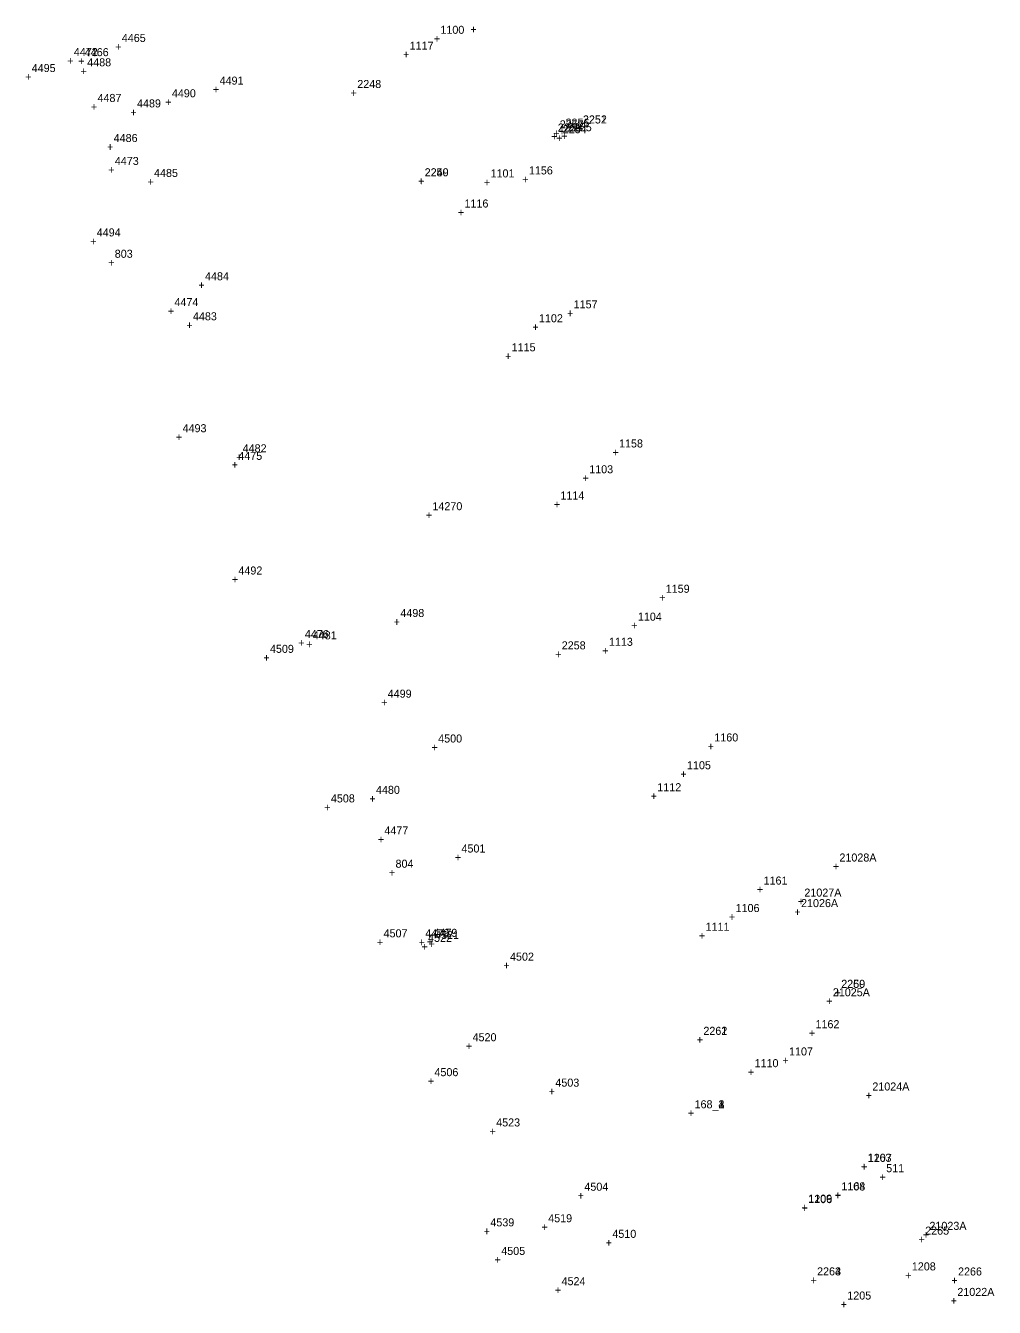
# Model space of a CAD drawing. Extents: x 1036751 to 1042192, y 772604 to 785439.
# Drawn here: x 1037008.7 to 1037310, y 782621.3 to 783020 of the extents above; entities that cross this region are included whole.
import ezdxf

# ---------------------------------------------------------------- set-up
doc = ezdxf.new("R2010")
doc.units = 0
for name, color, linetype in [('S_Control_Temp_Traverse', 7, 'Continuous'), ('S_Control_Traverse_Point', 7, 'Continuous'), ('S_Drainage_Culvert_Top', 7, 'Continuous'), ('S_Drainage_Invert', 7, 'Continuous'), ('S_Drainage_RipRap', 7, 'Continuous'), ('S_Ground_Elevation', 7, 'Continuous'), ('S_Roadway_Centerline', 7, 'Continuous'), ('S_Roadway_Edge_Pavement', 7, 'Continuous'), ('S_Roadway_Edge_TW', 7, 'Continuous'), ('S_Traffic_Sign_SinglePost', 7, 'Continuous'), ('S_Utilities_Pole_Power', 7, 'Continuous')]:
    doc.layers.add(name, color=color, linetype=linetype)

msp = doc.modelspace()

# ---------------------------------------------------------------- texts
at = {"layer": 'S_Control_Temp_Traverse'}
for s, p in [('803', (1037036.43, 782947.8)), ('803', (1037036.43, 782947.8)), ('803', (1037036.43, 782947.8)), ('803', (1037036.43, 782947.8)), ('+', (1037034.37, 782945.05)), ('+', (1037034.37, 782945.05)), ('+', (1037034.37, 782945.05)), ('+', (1037034.37, 782945.05)), ('+', (1037121.71, 782755.28)), ('+', (1037121.71, 782755.28)), ('+', (1037121.71, 782755.28)), ('+', (1037121.71, 782755.28)), ('804', (1037123.77, 782758.03)), ('804', (1037123.77, 782758.03)), ('804', (1037123.77, 782758.03)), ('804', (1037123.77, 782758.03)), ('168', (1037216.79, 782683.19)), ('168_1', (1037216.79, 782683.19)), ('168_3', (1037216.79, 782683.19)), ('168_2', (1037216.79, 782683.19)), ('168_4', (1037216.79, 782683.19)), ('+', (1037214.73, 782680.44)), ('+', (1037214.73, 782680.44)), ('+', (1037214.73, 782680.44)), ('+', (1037214.73, 782680.44)), ('+', (1037214.73, 782680.44))]:
    msp.add_text(s, height=2.5, dxfattribs=at).set_placement(p)
at = {"layer": 'S_Control_Traverse_Point'}
for s, p in [('511', (1037276.41, 782663.31)), ('511', (1037276.41, 782663.31)), ('511', (1037276.41, 782663.31)), ('511', (1037276.41, 782663.31)), ('511', (1037276.41, 782663.31)), ('+', (1037274.35, 782660.56)), ('+', (1037274.35, 782660.56)), ('+', (1037274.35, 782660.56)), ('+', (1037274.35, 782660.56)), ('+', (1037274.35, 782660.56))]:
    msp.add_text(s, height=2.5, dxfattribs=at).set_placement(p)
at = {"layer": 'S_Drainage_Culvert_Top'}
for s, p in [('+', (1037179.99, 782986.83)), ('2251', (1037182.05, 782989.58)), ('2250', (1037132.83, 782973.15)), ('+', (1037130.77, 782970.4)), ('2260', (1037262.4, 782720.64)), ('+', (1037260.34, 782717.89)), ('+', (1037217.47, 782703.28)), ('2261', (1037219.53, 782706.03)), ('2265', (1037288.53, 782643.88)), ('+', (1037286.47, 782641.13)), ('2264', (1037254.9, 782631.21)), ('+', (1037252.84, 782628.46))]:
    msp.add_text(s, height=2.5, dxfattribs=at).set_placement(p)
at = {"layer": 'S_Drainage_Invert'}
for s, p in [('+', (1037180.01, 782986.84)), ('2252', (1037182.07, 782989.59)), ('2249', (1037132.86, 782973.12)), ('+', (1037130.8, 782970.37)), ('2259', (1037262.43, 782720.66)), ('+', (1037260.37, 782717.91)), ('+', (1037217.48, 782703.3)), ('2262', (1037219.54, 782706.05)), ('2263', (1037254.9, 782631.19)), ('+', (1037252.84, 782628.44))]:
    msp.add_text(s, height=2.5, dxfattribs=at).set_placement(p)
at = {"layer": 'S_Drainage_RipRap'}
for s, p in [('21028A', (1037261.85, 782759.96)), ('+', (1037259.79, 782757.21)), ('21027A', (1037250.95, 782749.05)), ('+', (1037248.89, 782746.3)), ('21026A', (1037249.91, 782745.78)), ('+', (1037247.85, 782743.03)), ('+', (1037257.74, 782715.29)), ('21025A', (1037259.8, 782718.04)), ('21024A', (1037272.09, 782688.72)), ('+', (1037270.03, 782685.97)), ('21023A', (1037289.85, 782645.37)), ('+', (1037287.78, 782642.62)), ('21022A', (1037298.53, 782624.81)), ('+', (1037296.47, 782622.06))]:
    msp.add_text(s, height=2.5, dxfattribs=at).set_placement(p)
at = {"layer": 'S_Ground_Elevation'}
for s, p in [('4465', (1037038.62, 783014.94)), ('4466', (1037027.1, 783010.52)), ('+', (1037036.56, 783012.19)), ('+', (1037025.04, 783007.77)), ('4488', (1037027.87, 783007.36)), ('+', (1037025.81, 783004.61)), ('+', (1037066.98, 782998.92)), ('4491', (1037069.04, 783001.67)), ('4487', (1037031.06, 782996.27)), ('4489', (1037043.36, 782994.58)), ('+', (1037052.14, 782994.98)), ('4490', (1037054.2, 782997.73)), ('+', (1037029, 782993.52)), ('+', (1037041.3, 782991.83)), ('2253', (1037174.25, 782987.08)), ('2257', (1037174.85, 782988.07)), ('2254', (1037175.79, 782986.55)), ('2256', (1037176.64, 782988.6)), ('2255', (1037177.36, 782987.16)), ('4486', (1037036.09, 782983.81)), ('+', (1037172.18, 782984.33)), ('+', (1037172.79, 782985.32)), ('+', (1037173.73, 782983.8)), ('+', (1037174.58, 782985.85)), ('+', (1037175.3, 782984.41)), ('+', (1037034.03, 782981.06)), ('4485', (1037048.65, 782972.94)), ('+', (1037046.59, 782970.19)), ('4484', (1037064.51, 782940.8)), ('+', (1037062.45, 782938.05)), ('4483', (1037060.75, 782928.34)), ('+', (1037058.69, 782925.59)), ('4482', (1037076.21, 782887.27)), ('+', (1037074.15, 782884.52)), ('14270', (1037135.25, 782869.26)), ('+', (1037133.19, 782866.51)), ('4498', (1037125.27, 782836.03)), ('+', (1037123.21, 782833.28)), ('4481', (1037098.03, 782829.08)), ('+', (1037095.96, 782826.33)), ('4499', (1037121.34, 782810.94)), ('+', (1037119.28, 782808.19)), ('4500', (1037137.04, 782796.99)), ('+', (1037134.98, 782794.24)), ('4480', (1037117.69, 782781.01)), ('+', (1037115.63, 782778.26)), ('4501', (1037144.29, 782762.77)), ('+', (1037142.23, 782760.02)), ('4479', (1037135.57, 782736.53)), ('4521', (1037136.08, 782735.85)), ('+', (1037133.51, 782733.78)), ('+', (1037134.01, 782733.1)), ('4502', (1037159.38, 782729.12)), ('+', (1037157.32, 782726.37)), ('4520', (1037147.74, 782704.05)), ('+', (1037145.68, 782701.3)), ('4503', (1037173.49, 782689.92)), ('+', (1037171.43, 782687.17)), ('4504', (1037182.51, 782657.54)), ('+', (1037180.44, 782654.79)), ('4519', (1037171.26, 782647.73)), ('+', (1037169.2, 782644.98)), ('+', (1037189.15, 782640.13)), ('4510', (1037191.22, 782642.88))]:
    msp.add_text(s, height=2.5, dxfattribs=at).set_placement(p)
at = {"layer": 'S_Roadway_Centerline'}
for s, p in [('+', (1037135.67, 783014.73)), ('1100', (1037137.73, 783017.48)), ('1101', (1037153.33, 782972.8)), ('+', (1037151.27, 782970.05)), ('1102', (1037168.39, 782927.73)), ('+', (1037166.33, 782924.98)), ('1103', (1037184.02, 782880.75)), ('+', (1037181.96, 782878)), ('1104', (1037199.16, 782834.9)), ('+', (1037197.1, 782832.15)), ('1105', (1037214.44, 782788.67)), ('+', (1037212.38, 782785.92)), ('1106', (1037229.56, 782744.24)), ('+', (1037227.49, 782741.49)), ('1107', (1037246.18, 782699.63)), ('+', (1037244.12, 782696.88)), ('1108', (1037262.44, 782657.62)), ('1164', (1037262.5, 782657.7)), ('+', (1037260.38, 782654.87)), ('+', (1037260.44, 782654.95))]:
    msp.add_text(s, height=2.5, dxfattribs=at).set_placement(p)
at = {"layer": 'S_Roadway_Edge_Pavement'}
for s, p in [('+', (1037147.06, 783017.59)), ('1117', (1037128.16, 783012.54)), ('+', (1037126.1, 783009.79)), ('+', (1037163.19, 782970.98)), ('1156', (1037165.25, 782973.73)), ('1116', (1037145.22, 782963.43)), ('+', (1037143.16, 782960.68)), ('1157', (1037179.18, 782932.06)), ('+', (1037177.12, 782929.31)), ('1115', (1037159.9, 782918.7)), ('+', (1037157.84, 782915.95)), ('1158', (1037193.3, 782888.78)), ('+', (1037191.24, 782886.03)), ('1114', (1037175.06, 782872.59)), ('+', (1037173, 782869.84)), ('1159', (1037207.82, 782843.58)), ('+', (1037205.76, 782840.83)), ('1113', (1037190.15, 782827.07)), ('+', (1037188.09, 782824.32)), ('1160', (1037222.94, 782797.32)), ('+', (1037220.88, 782794.57)), ('+', (1037203.15, 782779.08)), ('1112', (1037205.21, 782781.83)), ('1161', (1037238.26, 782752.79)), ('+', (1037236.2, 782750.04)), ('+', (1037218.15, 782735.66)), ('1111', (1037220.21, 782738.41)), ('1162', (1037254.41, 782708.11)), ('+', (1037252.35, 782705.36)), ('1110', (1037235.46, 782695.98)), ('+', (1037233.4, 782693.23)), ('+', (1037268.54, 782663.82)), ('+', (1037268.64, 782663.76)), ('1163', (1037270.6, 782666.57)), ('1207', (1037270.7, 782666.51)), ('1109', (1037252.15, 782653.84)), ('1206', (1037252.16, 782653.68)), ('+', (1037250.09, 782651.09)), ('+', (1037250.1, 782650.93)), ('1208', (1037284.38, 782632.75)), ('+', (1037282.32, 782630)), ('1205', (1037264.3, 782623.69)), ('+', (1037262.24, 782620.94))]:
    msp.add_text(s, height=2.5, dxfattribs=at).set_placement(p)
at = {"layer": 'S_Roadway_Edge_TW'}
for s, p in [('4472', (1037023.7, 783010.58)), ('+', (1037021.64, 783007.83)), ('+', (1037008.54, 783002.84)), ('4495', (1037010.6, 783005.59)), ('4473', (1037036.45, 782976.67)), ('+', (1037034.39, 782973.92)), ('4494', (1037030.83, 782954.44)), ('+', (1037028.76, 782951.69)), ('4474', (1037055, 782932.75)), ('+', (1037052.94, 782930)), ('+', (1037055.47, 782890.77)), ('4493', (1037057.53, 782893.52)), ('4475', (1037074.86, 782884.92)), ('+', (1037072.8, 782882.17)), ('4492', (1037074.9, 782849.26)), ('+', (1037072.84, 782846.51)), ('4476', (1037095.57, 782829.5)), ('4509', (1037084.71, 782824.88)), ('+', (1037093.5, 782826.75)), ('+', (1037082.65, 782822.13)), ('+', (1037101.6, 782775.6)), ('4508', (1037103.66, 782778.35)), ('4477', (1037120.3, 782768.38)), ('+', (1037118.24, 782765.63)), ('4507', (1037120.05, 782736.38)), ('4478', (1037133.02, 782736.37)), ('4522', (1037133.89, 782734.96)), ('+', (1037117.99, 782733.63)), ('+', (1037130.96, 782733.62)), ('+', (1037131.83, 782732.21)), ('4506', (1037135.88, 782693.18)), ('+', (1037133.82, 782690.43)), ('4523', (1037155.08, 782677.54)), ('+', (1037153.02, 782674.79)), ('+', (1037151.2, 782643.7)), ('4539', (1037153.27, 782646.45)), ('4505', (1037156.66, 782637.57)), ('+', (1037154.6, 782634.82)), ('4524', (1037175.42, 782628.15)), ('+', (1037173.36, 782625.4))]:
    msp.add_text(s, height=2.5, dxfattribs=at).set_placement(p)
at = {"layer": 'S_Traffic_Sign_SinglePost'}
for s, p in [('2266', (1037298.75, 782631.17)), ('+', (1037296.69, 782628.42))]:
    msp.add_text(s, height=2.5, dxfattribs=at).set_placement(p)
at = {"layer": 'S_Utilities_Pole_Power'}
for s, p in [('2248', (1037111.87, 783000.61)), ('+', (1037109.8, 782997.86)), ('+', (1037173.41, 782823.22)), ('2258', (1037175.47, 782825.97))]:
    msp.add_text(s, height=2.5, dxfattribs=at).set_placement(p)

doc.saveas('drawing.dxf')
